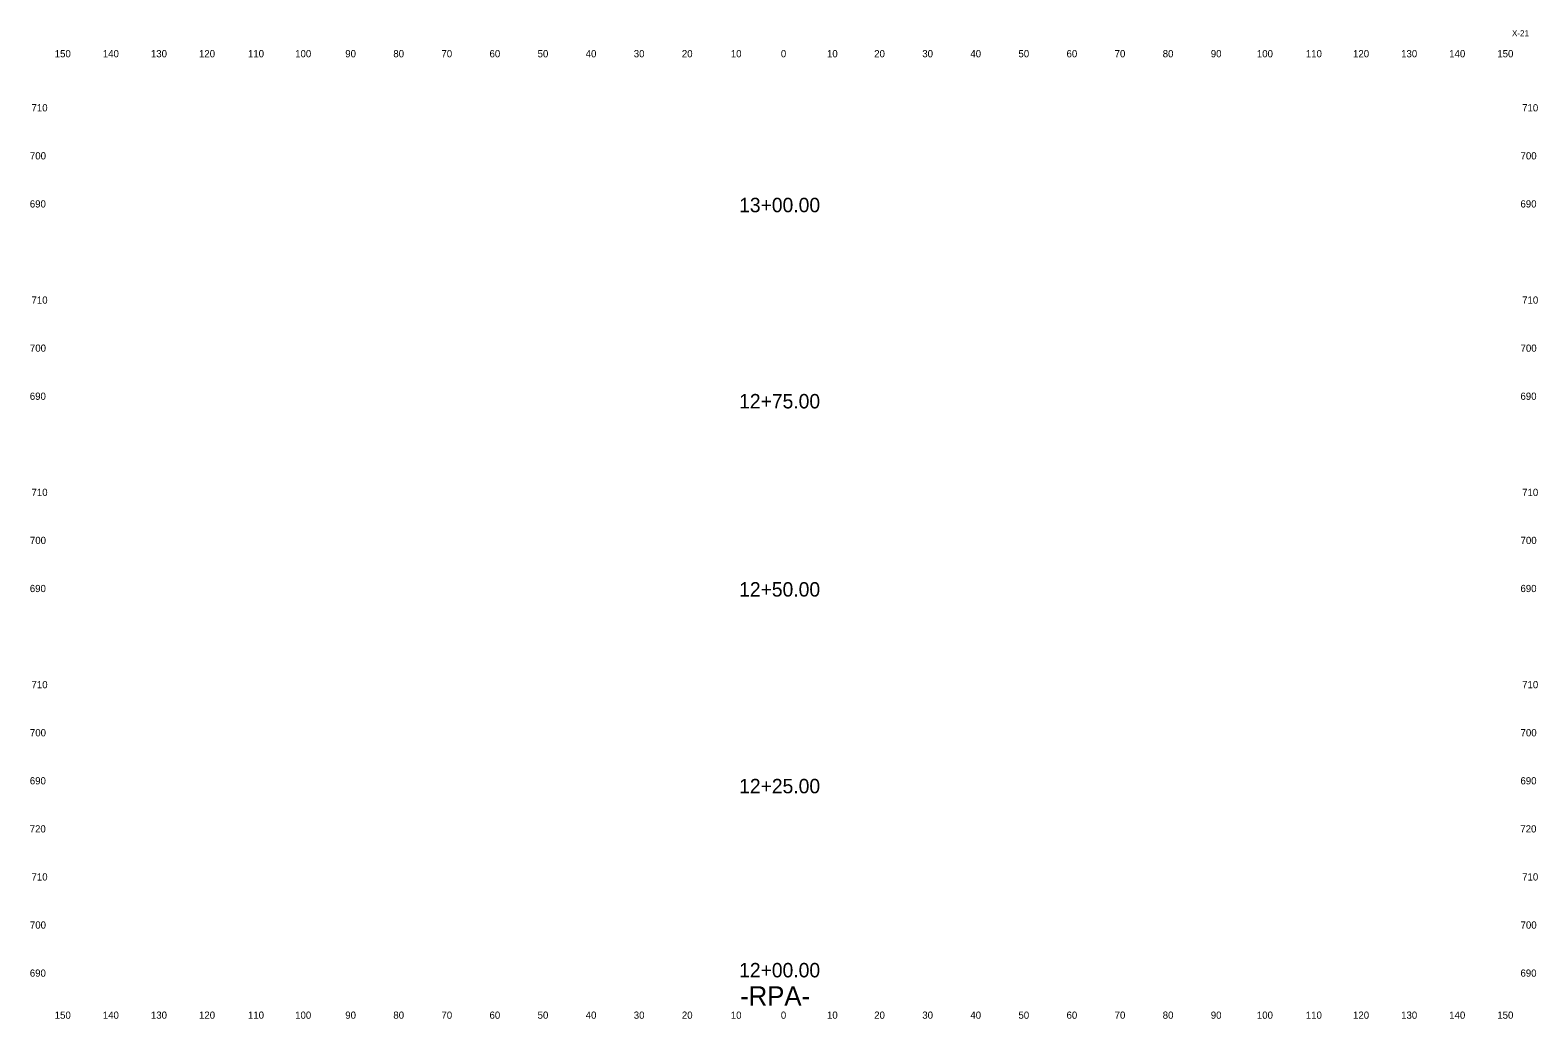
# Model space of a CAD drawing. Extents: x 3 to 317, y 1 to 867.
# Drawn here: x 3.3 to 316.9, y 441.2 to 646.9 of the extents above; entities that cross this region are included whole.
import ezdxf

# ---------------------------------------------------------------- set-up
doc = ezdxf.new("R2010")
doc.units = 0
for name, color, linetype in [('Prop XS Alignment Label', 7, 'Continuous'), ('Prop XS Elevation Labels', 7, 'Continuous'), ('Prop XS Offset Labels', 7, 'Continuous'), ('Prop XS Sheet Number', 7, 'Continuous'), ('Prop XS Station Labels', 7, 'Continuous')]:
    doc.layers.add(name, color=color, linetype=linetype)

msp = doc.modelspace()

# ---------------------------------------------------------------- texts
at = {"layer": 'Prop XS Alignment Label'}
msp.add_text('-RPA-', height=4, dxfattribs=at).set_placement((150.97, 444))
at = {"layer": 'Prop XS Elevation Labels'}
for s, p in [('710', (3.61, 630)), ('710', (313.61, 630)), ('700', (3.28, 620)), ('700', (313.28, 620)), ('690', (3.26, 610)), ('690', (313.26, 610)), ('710', (3.61, 590)), ('710', (313.61, 590)), ('700', (3.28, 580)), ('700', (313.28, 580)), ('690', (3.26, 570)), ('690', (313.26, 570)), ('710', (3.61, 550)), ('710', (313.61, 550)), ('700', (3.28, 540)), ('700', (313.28, 540)), ('690', (3.26, 530)), ('690', (313.26, 530)), ('710', (3.61, 510)), ('710', (313.61, 510)), ('700', (3.28, 500)), ('700', (313.28, 500)), ('690', (3.26, 490)), ('690', (313.26, 490)), ('720', (3.23, 480)), ('720', (313.23, 480)), ('710', (3.61, 470)), ('710', (313.61, 470)), ('700', (3.28, 460)), ('700', (313.28, 460)), ('690', (3.26, 450)), ('690', (313.26, 450))]:
    msp.add_text(s, height=1.5, dxfattribs=at).set_placement(p)
at = {"layer": 'Prop XS Offset Labels'}
for s, p in [('150', (8.44, 641.25)), ('140', (18.44, 641.25)), ('130', (28.44, 641.25)), ('120', (38.44, 641.25)), ('110', (48.62, 641.25)), ('100', (58.44, 641.25)), ('90', (68.86, 641.25)), ('80', (78.86, 641.25)), ('70', (88.86, 641.25)), ('60', (98.86, 641.25)), ('50', (108.86, 641.25)), ('40', (118.86, 641.25)), ('30', (128.86, 641.25)), ('20', (138.86, 641.25)), ('10', (149.04, 641.25)), ('0', (159.45, 641.25)), ('10', (169.04, 641.25)), ('20', (178.86, 641.25)), ('30', (188.86, 641.25)), ('40', (198.86, 641.25)), ('50', (208.86, 641.25)), ('60', (218.86, 641.25)), ('70', (228.86, 641.25)), ('80', (238.86, 641.25)), ('90', (248.86, 641.25)), ('100', (258.44, 641.25)), ('110', (268.62, 641.25)), ('120', (278.44, 641.25)), ('130', (288.44, 641.25)), ('140', (298.44, 641.25)), ('150', (308.44, 641.25)), ('150', (8.44, 441.25)), ('140', (18.44, 441.25)), ('130', (28.44, 441.25)), ('120', (38.44, 441.25)), ('110', (48.62, 441.25)), ('100', (58.44, 441.25)), ('90', (68.86, 441.25)), ('80', (78.86, 441.25)), ('70', (88.86, 441.25)), ('60', (98.86, 441.25)), ('50', (108.86, 441.25)), ('40', (118.86, 441.25)), ('30', (128.86, 441.25)), ('20', (138.86, 441.25)), ('10', (149.04, 441.25)), ('0', (159.45, 441.25)), ('10', (169.04, 441.25)), ('20', (178.86, 441.25)), ('30', (188.86, 441.25)), ('40', (198.86, 441.25)), ('50', (208.86, 441.25)), ('60', (218.86, 441.25)), ('70', (228.86, 441.25)), ('80', (238.86, 441.25)), ('90', (248.86, 441.25)), ('100', (258.44, 441.25)), ('110', (268.62, 441.25)), ('120', (278.44, 441.25)), ('130', (288.44, 441.25)), ('140', (298.44, 441.25)), ('150', (308.44, 441.25))]:
    msp.add_text(s, height=1.5, dxfattribs=at).set_placement(p)
at = {"layer": 'Prop XS Sheet Number'}
msp.add_text('X-21', height=1.25, dxfattribs=at).set_placement((311.5, 645.63))
at = {"layer": 'Prop XS Station Labels'}
for s, p in [('13+00.00', (150.77, 609.02)), ('12+75.00', (150.77, 568.21)), ('12+50.00', (150.77, 529.07)), ('12+25.00', (150.77, 488.15)), ('12+00.00', (150.77, 449.86))]:
    msp.add_text(s, height=3, dxfattribs=at).set_placement(p)

doc.saveas('drawing.dxf')
